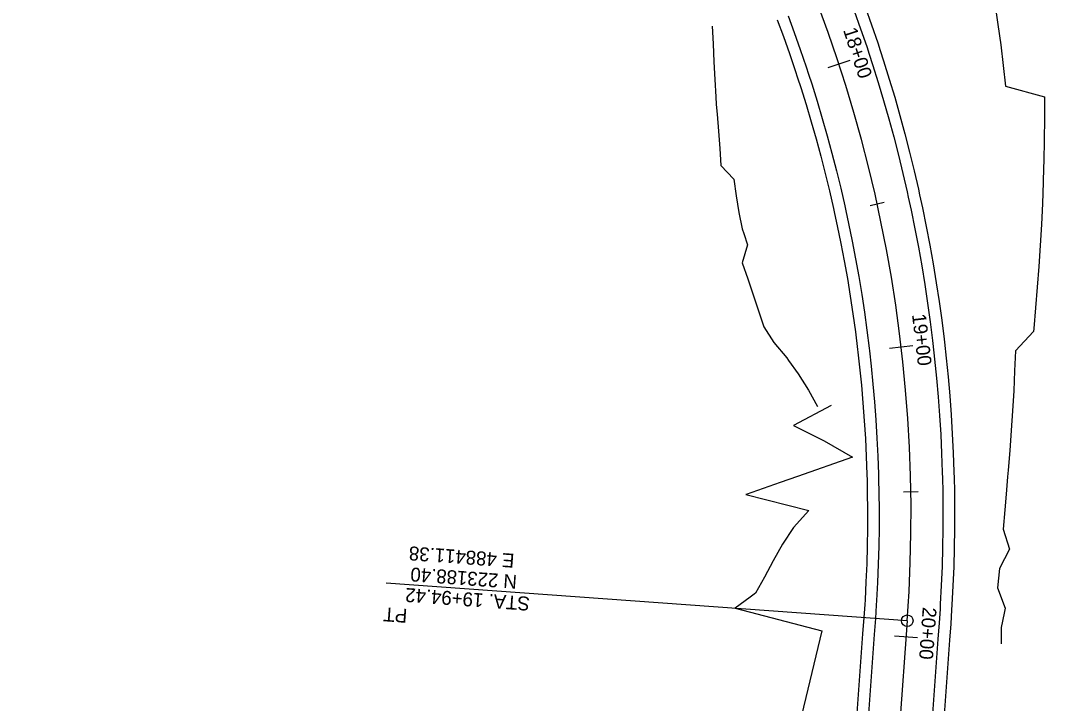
# Model space of a CAD drawing. Extents: x 487756 to 488722, y 222467 to 224000.
# Drawn here: x 488105.8 to 488458.7, y 223159.9 to 223395.2 of the extents above; entities that cross this region are included whole.
import ezdxf

# ---------------------------------------------------------------- set-up
doc = ezdxf.new("R2010")
doc.units = 0
for name, color, linetype in [('HM-SMOD-BRK LINE', 7, 'Continuous'), ('HR-FEAT-CUT', 7, 'Continuous'), ('HR-FEAT-EOR', 7, 'Continuous'), ('HR-FEAT-FILL', 7, 'Continuous'), ('HR-GMSC-HOR_VER ALN', 7, 'Continuous'), ('HR-GMSC-PCPT SYMB', 7, 'Continuous'), ('HR-GPLN-CL STA', 7, 'Continuous'), ('HR-GPLN-CL TICKS', 7, 'Continuous'), ('HR-GPLN-PCPT LDR', 7, 'Continuous'), ('HR-GPLN-PCPT TXT', 7, 'Continuous'), ('SV_MISC_MISC_TOPO', 7, 'Continuous')]:
    doc.layers.add(name, color=color, linetype=linetype)

msp = doc.modelspace()

# ---------------------------------------------------------------- linework, layer by layer
at = {"layer": 'HM-SMOD-BRK LINE'}
for points in [[(488370.29, 223396.86), (488372.44, 223391.03), (488374.52, 223385.16), (488376.53, 223379.28), (488377.37, 223376.73), (488378.46, 223373.36), (488380.32, 223367.43), (488382.1, 223361.47), (488383.8, 223355.49), (488385.43, 223349.48), (488386.98, 223343.46), (488388.46, 223337.42), (488389.86, 223331.36), (488390.25, 223329.58), (488391.18, 223325.28), (488392.42, 223319.18), (488393.59, 223313.07), (488394.67, 223306.95), (488395.68, 223300.81), (488396.62, 223294.66), (488397.47, 223288.5), (488398.24, 223282.33), (488398.36, 223281.37), (488398.94, 223276.15), (488399.56, 223269.96), (488400.1, 223263.76), (488400.56, 223257.56), (488400.94, 223251.35), (488401.24, 223245.14), (488401.47, 223238.92), (488401.52, 223236.89), (488401.61, 223232.7), (488401.61, 223232.6), (488401.67, 223226.48), (488401.66, 223220.26), (488401.57, 223214.05), (488401.39, 223207.83), (488401.14, 223201.61), (488400.81, 223195.4), (488400.71, 223193.75), (488400.4, 223189.2), (488400, 223183.62), (488396.39, 223133.76)], [(488393.13, 223398.52), (488395.3, 223392.39), (488397.4, 223386.24), (488398.28, 223383.58), (488399.42, 223380.06), (488401.36, 223373.86), (488403.22, 223367.63), (488405, 223361.38), (488406.7, 223355.11), (488408.32, 223348.81), (488409.86, 223342.5), (488411.32, 223336.16), (488411.74, 223334.3), (488412.7, 223329.81), (488414, 223323.44), (488415.22, 223317.06), (488416.36, 223310.66), (488417.41, 223304.25), (488418.39, 223297.82), (488419.28, 223291.38), (488420.09, 223284.93), (488420.21, 223283.93), (488420.82, 223278.47), (488421.46, 223272.01), (488422.03, 223265.53), (488422.51, 223259.05), (488422.91, 223252.56), (488423.22, 223246.07), (488423.46, 223239.57), (488423.51, 223237.45), (488423.61, 223233.07), (488423.61, 223232.97), (488423.67, 223226.57), (488423.66, 223220.08), (488423.56, 223213.58), (488423.38, 223207.08), (488423.12, 223200.58), (488422.77, 223194.09), (488422.67, 223192.36), (488422.35, 223187.61), (488421.94, 223182.04), (488418.34, 223132.17)]]:
    msp.add_lwpolyline(points, dxfattribs=at)
at = {"layer": 'HR-FEAT-CUT'}
for points in [[(488442, 223397.9), (488442.65, 223393.88), (488443.65, 223386.79), (488444.49, 223379.67), (488445.2, 223372.56), (488458.69, 223368.85), (488458.63, 223361.43), (488458.57, 223354.06), (488458.44, 223346.72), (488458.38, 223344.57), (488458.24, 223339.4), (488457.98, 223332.13), (488457.67, 223324.88), (488457.22, 223317.65), (488456.71, 223310.46), (488456.17, 223303.3), (488455.6, 223296.18), (488454.99, 223289.09), (488454.89, 223288), (488448.63, 223281.43), (488448.37, 223274.52), (488448.06, 223267.63), (488447.68, 223260.75), (488447.24, 223253.9), (488446.73, 223247.06), (488446.13, 223240.24), (488445.92, 223238.02), (488445.58, 223233.44), (488445.57, 223233.33), (488445.02, 223226.66), (488444.4, 223219.9), (488446.57, 223213.08), (488443.16, 223206.4), (488442.45, 223199.68), (488445.13, 223192.76), (488444.78, 223190.97), (488443.76, 223186.06), (488443.72, 223180.46)], [(488344.14, 223393.31), (488344.45, 223387.13), (488344.76, 223381), (488345.07, 223374.92), (488345.39, 223368.88), (488345.54, 223366.3), (488345.82, 223362.93), (488346.29, 223357.03), (488346.73, 223351.15), (488347.15, 223345.29), (488351.59, 223340.54), (488352.36, 223334.77), (488353.31, 223329.07), (488354.46, 223323.43), (488355, 223321.82), (488356.3, 223317.93), (488354.49, 223311.7), (488356.39, 223306.22), (488358.28, 223300.72), (488360.14, 223295.2), (488361.99, 223289.64), (488365.44, 223284.27), (488369.88, 223278.95), (488370.48, 223278.11), (488373.76, 223273.47), (488377.4, 223267.89), (488380.39, 223262.17)]]:
    msp.add_lwpolyline(points, dxfattribs=at)
at = {"layer": 'HR-FEAT-EOR'}
for points in [[(488396.89, 223399.88), (488399.08, 223393.71), (488401.19, 223387.51), (488402.08, 223384.82), (488403.23, 223381.28), (488405.18, 223375.03), (488407.06, 223368.75), (488408.85, 223362.45), (488410.57, 223356.13), (488412.2, 223349.79), (488413.76, 223343.42), (488415.23, 223337.04), (488415.64, 223335.16), (488416.62, 223330.64), (488417.93, 223324.22), (488419.16, 223317.78), (488420.3, 223311.33), (488421.37, 223304.87), (488422.35, 223298.39), (488423.25, 223291.9), (488424.06, 223285.41), (488424.18, 223284.4), (488424.8, 223278.9), (488425.45, 223272.38), (488426.01, 223265.85), (488426.5, 223259.32), (488426.9, 223252.78), (488427.22, 223246.24), (488427.45, 223239.69), (488427.51, 223237.55), (488427.61, 223233.14), (488427.61, 223233.03), (488427.67, 223226.59), (488427.66, 223220.04), (488427.56, 223213.49), (488427.38, 223206.94), (488427.12, 223200.4), (488426.77, 223193.86), (488426.66, 223192.11), (488426.34, 223187.32), (488425.93, 223181.75), (488422.32, 223131.88)], [(488366.54, 223395.45), (488368.68, 223389.66), (488370.75, 223383.85), (488372.74, 223378.01), (488373.57, 223375.48), (488374.65, 223372.15), (488376.49, 223366.26), (488378.26, 223360.35), (488379.95, 223354.41), (488381.56, 223348.46), (488383.1, 223342.49), (488384.57, 223336.49), (488385.95, 223330.48), (488386.35, 223328.72), (488387.26, 223324.45), (488388.5, 223318.41), (488389.65, 223312.35), (488390.73, 223306.27), (488391.73, 223300.19), (488392.66, 223294.09), (488393.5, 223287.98), (488394.27, 223281.86), (488394.38, 223280.91), (488394.96, 223275.73), (488395.58, 223269.59), (488396.11, 223263.44), (488396.57, 223257.29), (488396.95, 223251.13), (488397.25, 223244.97), (488397.47, 223238.8), (488397.52, 223236.79), (488397.61, 223232.64), (488397.61, 223232.54), (488397.67, 223226.47), (488397.66, 223220.3), (488397.57, 223214.13), (488397.4, 223207.96), (488397.15, 223201.8), (488396.82, 223195.64), (488396.72, 223194), (488396.41, 223189.48), (488396.01, 223183.91), (488392.4, 223134.04)]]:
    msp.add_lwpolyline(points, dxfattribs=at)
at = {"layer": 'HR-FEAT-FILL'}
msp.add_lwpolyline([(488385.15, 223262.56), (488372.16, 223255.63), (488382.73, 223250.35), (488392.46, 223244.77), (488373.56, 223238.1), (488367.59, 223236.03), (488355.88, 223231.94), (488355.7, 223231.84), (488377.51, 223226.39), (488372.12, 223220.52), (488368.34, 223214.75), (488365.16, 223209.06), (488362.17, 223203.44), (488359.13, 223197.89), (488357.22, 223196.49), (488352.09, 223192.69), (488381.95, 223184.93), (488370.13, 223135.66)], dxfattribs=at)
at = {"layer": 'HR-GMSC-HOR_VER ALN'}
msp.add_line((488411.38, 223188.4), (488399.31, 223021.63), dxfattribs=at)
msp.add_arc((487912.68, 223224.48), 500, 355.8619, 67.2843, dxfattribs=at)
at = {"layer": 'HR-GMSC-PCPT SYMB'}
msp.add_circle((488411.38, 223188.4), 2, dxfattribs=at)
at = {"layer": 'HR-GPLN-CL TICKS'}
for points in [[(488391.63, 223381.4), (488384.03, 223378.91)], [(488403.44, 223332.48), (488398.55, 223331.4)], [(488413.26, 223283.12), (488405.31, 223282.19)], [(488415.11, 223232.83), (488410.11, 223232.74)], [(488414.96, 223182.54), (488406.98, 223183.12)]]:
    msp.add_lwpolyline(points, dxfattribs=at)
at = {"layer": 'HR-GPLN-PCPT LDR'}
msp.add_lwpolyline([(488411.38, 223188.4), (488231.84, 223201.39)], dxfattribs=at)
at = {"layer": 'SV_MISC_MISC_TOPO'}
for p, q in [((488344.14, 223393.31), (488344.14, 223393.31)), ((488442.65, 223393.88), (488442.65, 223393.88)), ((488344.45, 223387.13), (488344.45, 223387.13)), ((488443.65, 223386.79), (488443.65, 223386.79)), ((488344.76, 223381), (488344.76, 223381)), ((488444.49, 223379.67), (488444.49, 223379.67)), ((488345.07, 223374.92), (488345.07, 223374.92)), ((488445.2, 223372.56), (488445.2, 223372.56)), ((488345.39, 223368.88), (488345.39, 223368.88)), ((488458.69, 223368.85), (488458.69, 223368.85)), ((488345.54, 223366.3), (488345.54, 223366.3)), ((488345.82, 223362.93), (488345.82, 223362.93)), ((488458.63, 223361.43), (488458.63, 223361.43)), ((488346.29, 223357.03), (488346.29, 223357.03)), ((488458.57, 223354.06), (488458.57, 223354.06)), ((488346.73, 223351.15), (488346.73, 223351.15)), ((488458.44, 223346.72), (488458.44, 223346.72)), ((488347.15, 223345.29), (488347.15, 223345.29)), ((488458.38, 223344.57), (488458.38, 223344.57)), ((488351.59, 223340.54), (488351.59, 223340.54)), ((488458.24, 223339.4), (488458.24, 223339.4)), ((488352.36, 223334.77), (488352.36, 223334.77)), ((488353.31, 223329.07), (488353.31, 223329.07)), ((488457.98, 223332.13), (488457.98, 223332.13)), ((488354.46, 223323.43), (488354.46, 223323.43)), ((488355, 223321.82), (488355, 223321.82)), ((488457.67, 223324.88), (488457.67, 223324.88)), ((488356.3, 223317.93), (488356.3, 223317.93)), ((488457.22, 223317.65), (488457.22, 223317.65)), ((488354.49, 223311.7), (488354.49, 223311.7)), ((488456.71, 223310.46), (488456.71, 223310.46)), ((488356.39, 223306.22), (488356.39, 223306.22)), ((488358.28, 223300.72), (488358.28, 223300.72)), ((488456.17, 223303.3), (488456.17, 223303.3)), ((488360.14, 223295.2), (488360.14, 223295.2)), ((488455.6, 223296.18), (488455.6, 223296.18)), ((488361.99, 223289.64), (488361.99, 223289.64)), ((488454.89, 223288), (488454.89, 223288)), ((488454.99, 223289.09), (488454.99, 223289.09)), ((488365.44, 223284.27), (488365.44, 223284.27)), ((488448.63, 223281.43), (488448.63, 223281.43)), ((488369.88, 223278.95), (488369.88, 223278.95)), ((488370.48, 223278.11), (488370.48, 223278.11)), ((488373.76, 223273.47), (488373.76, 223273.47)), ((488448.37, 223274.52), (488448.37, 223274.52)), ((488377.4, 223267.89), (488377.4, 223267.89)), ((488448.06, 223267.63), (488448.06, 223267.63)), ((488380.39, 223262.17), (488380.39, 223262.17)), ((488447.68, 223260.75), (488447.68, 223260.75)), ((488372.16, 223255.63), (488372.16, 223255.63)), ((488447.24, 223253.9), (488447.24, 223253.9)), ((488382.73, 223250.35), (488382.73, 223250.35)), ((488392.46, 223244.77), (488392.46, 223244.77)), ((488446.73, 223247.06), (488446.73, 223247.06)), ((488373.56, 223238.1), (488373.56, 223238.1)), ((488445.92, 223238.02), (488445.92, 223238.02)), ((488446.13, 223240.24), (488446.13, 223240.24)), ((488367.59, 223236.03), (488367.59, 223236.03)), ((488355.7, 223231.84), (488355.7, 223231.84)), ((488355.88, 223231.94), (488355.88, 223231.94)), ((488445.57, 223233.33), (488445.57, 223233.33)), ((488445.58, 223233.44), (488445.58, 223233.44)), ((488445.02, 223226.66), (488445.02, 223226.66)), ((488377.51, 223226.39), (488377.51, 223226.39)), ((488372.12, 223220.52), (488372.12, 223220.52)), ((488444.4, 223219.9), (488444.4, 223219.9)), ((488368.34, 223214.75), (488368.34, 223214.75)), ((488446.57, 223213.08), (488446.57, 223213.08)), ((488365.16, 223209.06), (488365.16, 223209.06)), ((488443.16, 223206.4), (488443.16, 223206.4)), ((488362.17, 223203.44), (488362.17, 223203.44)), ((488442.45, 223199.68), (488442.45, 223199.68)), ((488357.22, 223196.49), (488357.22, 223196.49)), ((488359.13, 223197.89), (488359.13, 223197.89)), ((488352.09, 223192.69), (488352.09, 223192.69)), ((488445.13, 223192.76), (488445.13, 223192.76)), ((488444.78, 223190.97), (488444.78, 223190.97)), ((488381.95, 223184.93), (488381.95, 223184.93)), ((488443.76, 223186.06), (488443.76, 223186.06)), ((488443.72, 223180.46), (488443.72, 223180.46))]:
    msp.add_line(p, q, dxfattribs=at)

# ---------------------------------------------------------------- texts
at = {"layer": 'HR-GPLN-CL STA'}
for s, rotation, p in [('18+00', 288.1403, (488389.23, 223391.92)), ('19+00', 276.6811, (488413, 223293.9)), ('20+00', 265.8619, (488416.73, 223193.18))]:
    msp.add_text(s, height=4.8, rotation=rotation, dxfattribs=at).set_placement(p)
at = {"layer": 'HR-GPLN-PCPT TXT'}
for s, p in [('E 488411.38', (488276.12, 223211.42)), ('N 223188.40', (488277.01, 223204.14)), ('STA. 19+94.42', (488281.45, 223196.6)), ('PT ', (488239.22, 223192.43))]:
    msp.add_text(s, height=4.8, rotation=175.8619, dxfattribs=at).set_placement(p)

doc.saveas('drawing.dxf')
